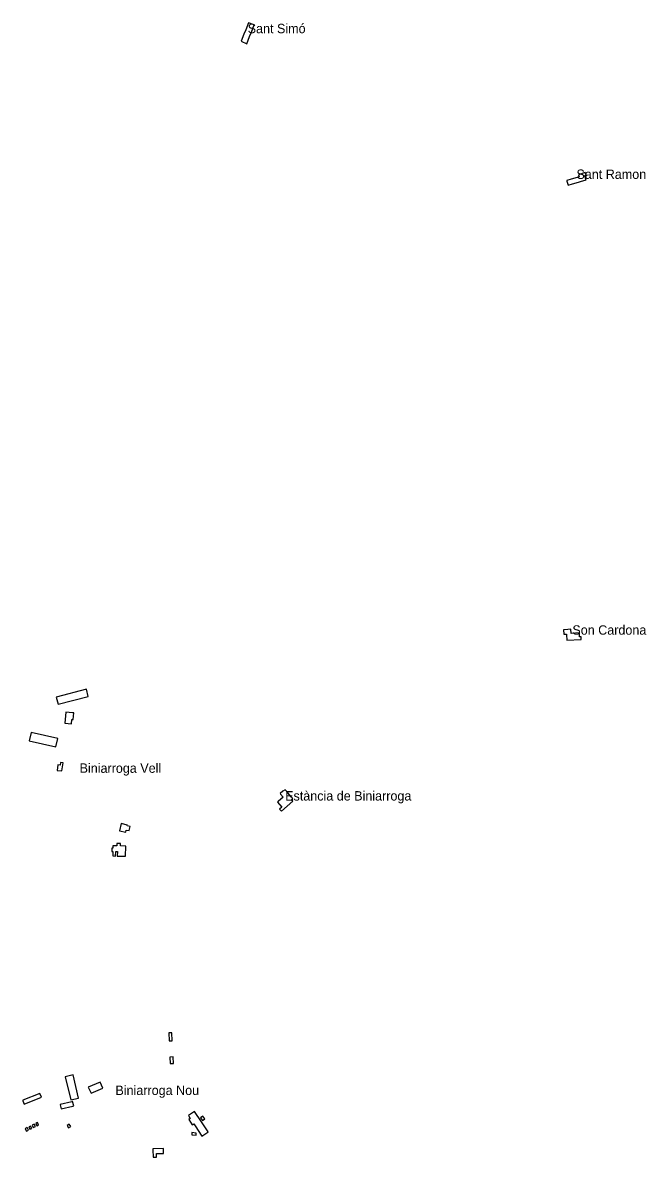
# Model space of a CAD drawing. Extents: x 599451 to 612034, y 4411179 to 4428219.
# Drawn here: x 603982 to 604780, y 4420208 to 4421659 of the extents above; entities that cross this region are included whole.
import ezdxf

# ---------------------------------------------------------------- set-up
doc = ezdxf.new("R2010")
doc.units = 0
doc.layers.add('Bé Arquitectònic', color=7, linetype='Continuous')

msp = doc.modelspace()

# ---------------------------------------------------------------- linework, layer by layer
at = {"layer": 'Bé Arquitectònic'}
for points in [[(604265.3, 4421644.9), (604261.7, 4421635.8), (604269, 4421632.6), (604272.7, 4421641.9), (604275, 4421647.5), (604278.6, 4421656.5), (604271.1, 4421659.4), (604267.6, 4421650.5)], [(604683.8, 4421459.2), (604678.3, 4421457.5), (604678.5, 4421456.9), (604680.1, 4421451.5), (604685.7, 4421453.2), (604693.4, 4421455.6), (604695.9, 4421456.3), (604703, 4421458.5), (604702.9, 4421459), (604701.5, 4421463.8), (604702, 4421463.9), (604703.1, 4421464.3), (604702, 4421467.7), (604693.2, 4421465), (604694, 4421462.3), (604691.6, 4421461.6)], [(604683.9, 4420878.2), (604683.6, 4420883.4), (604679.6, 4420883.2), (604674.2, 4420882.9), (604674.5, 4420877), (604678.1, 4420877.2), (604678.1, 4420876.5), (604678.5, 4420869.5), (604696.8, 4420870.5), (604696.6, 4420873.9), (604694.7, 4420873.8), (604694.4, 4420878.7)], [(604066.1, 4420797.5), (604063.9, 4420806.6), (604025.2, 4420796.4), (604027.6, 4420787.6)], [(604036.2, 4420763.1), (604044.9, 4420762.4), (604045.4, 4420768), (604046.8, 4420767.9), (604047.6, 4420776.3), (604046.1, 4420776.5), (604037.5, 4420777.4)], [(603993.1, 4420751.3), (603990.8, 4420740.7), (604024.9, 4420733.1), (604027.3, 4420743.7)], [(604034.1, 4420712.6), (604030.9, 4420713.1), (604030.3, 4420709.5), (604027.5, 4420710), (604026.5, 4420702.9), (604032.6, 4420702.2)], [(604309.2, 4420663.2), (604308.2, 4420662.3), (604313.8, 4420655.9), (604311, 4420653.4), (604313.3, 4420650.8), (604327.9, 4420663.7), (604326.3, 4420665.5), (604327.8, 4420666.9), (604326.1, 4420668.7), (604321.5, 4420674), (604318.2, 4420677.8), (604315.3, 4420676.2), (604311.7, 4420673.1), (604312.2, 4420672.5), (604315.5, 4420668.7)], [(604116.1, 4420631.9), (604116.3, 4420633), (604108.5, 4420634.8), (604106.4, 4420625.7), (604114.2, 4420623.8), (604114.8, 4420626.6), (604118.4, 4420625.8), (604119.7, 4420631)], [(604097.8, 4420603.4), (604096.6, 4420603.5), (604096.5, 4420599.2), (604097.7, 4420599.2), (604097.6, 4420593.4), (604101.2, 4420593.3), (604101.4, 4420599.1), (604103.5, 4420599.1), (604103.3, 4420593.3), (604113.9, 4420593), (604114.3, 4420606), (604107.5, 4420606.2), (604107.6, 4420609.2), (604102.8, 4420609.3), (604102.7, 4420606.3), (604097.9, 4420606.4)], [(604169.8, 4420356.7), (604173.7, 4420356.8), (604173.3, 4420367.3), (604169.4, 4420367)], [(604170.6, 4420336), (604171.2, 4420327.9), (604175.3, 4420328), (604175, 4420336.3)], [(604043.8, 4420281.2), (604053.9, 4420283.6), (604046.8, 4420313.5), (604036.7, 4420311)], [(604069.8, 4420289.8), (604084.7, 4420296.5), (604081.4, 4420304), (604066.1, 4420297.7)], [(603982.6, 4420280.2), (603984.3, 4420275.9), (604006.3, 4420284.7), (604004.7, 4420288.7), (604004.3, 4420289.6), (603982.4, 4420280.8)], [(604030.5, 4420275.2), (604031.6, 4420269.9), (604046.4, 4420273.3), (604047.6, 4420273.6), (604046.3, 4420279.2), (604045.2, 4420278.9), (604030.4, 4420275.5)], [(604211, 4420253.2), (604202.1, 4420266.3), (604194.3, 4420261.4), (604194.9, 4420260.5), (604196.8, 4420257.7), (604194.7, 4420256.3), (604199.2, 4420249.6), (604201.2, 4420250.9), (604203.1, 4420248), (604211.6, 4420235.1), (604219.1, 4420240.1), (604219.7, 4420240.5)], [(604215.3, 4420257), (604212.8, 4420260.5), (604210, 4420258.5), (604212.4, 4420255.1)], [(603988.3, 4420245.8), (603985.6, 4420244.4), (603987.1, 4420241.4), (603989.8, 4420242.8)], [(603991.6, 4420243.7), (603993.9, 4420244.9), (603992.4, 4420247.9), (603990.1, 4420246.7)], [(603995.8, 4420245.9), (603998.6, 4420247.3), (603997.1, 4420250.3), (603994.3, 4420248.9)], [(604000.6, 4420248.3), (604002.8, 4420249.5), (604001.4, 4420252.5), (603999, 4420251.3)], [(604043.9, 4420247.2), (604041.9, 4420250.2), (604039.1, 4420248.4), (604041.1, 4420245.4)], [(604204.1, 4420236.3), (604204.4, 4420238.9), (604198.6, 4420239.5), (604198.6, 4420236.5)], [(604148.7, 4420217.5), (604149.1, 4420207.9), (604153.5, 4420208), (604153.4, 4420212.7), (604162.7, 4420212.9), (604162.6, 4420218.4), (604162.6, 4420219.1), (604148.7, 4420218.5)]]:
    msp.add_lwpolyline(points, close=True, dxfattribs=at)

# ---------------------------------------------------------------- texts
for s, p in [('Sant Simó', (604270.2, 4421646)), ('Sant Ramon', (604690.7, 4421459.6)), ('Son Cardona', (604685.5, 4420876.5)), ('Biniarroga Vell', (604055.2, 4420699.8)), ('Estància de Biniarroga', (604318.1, 4420664.3)), ('Biniarroga Nou', (604101, 4420287.6))]:
    msp.add_text(s, height=12, dxfattribs=at).set_placement(p)

doc.saveas('drawing.dxf')
